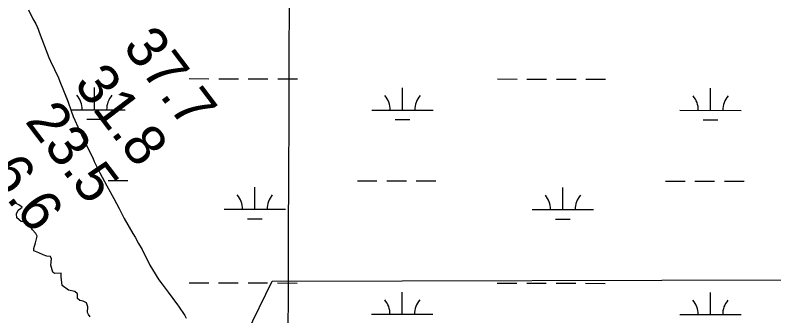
# Model space of a CAD drawing. Extents: x 3148686 to 3186545, y 916144 to 941516.
# Drawn here: x 3160368 to 3161603, y 939203 to 939693 of the extents above; entities that cross this region are included whole.
import ezdxf

# ---------------------------------------------------------------- set-up
doc = ezdxf.new("R2010")
doc.units = 0
for name, color, linetype in [('V-GRID-MAJR', 7, 'Continuous'), ('V-RIVR-EDGE', 7, 'Continuous'), ('V-RIVR-RANG', 7, 'Continuous'), ('V-SITE-VEGE', 7, 'Continuous'), ('V-TOPO-BNDY', 7, 'Continuous'), ('V-WETL-SWMP', 7, 'Continuous')]:
    doc.layers.add(name, color=color, linetype=linetype)

msp = doc.modelspace()

# ---------------------------------------------------------------- linework, layer by layer
at = {"layer": 'V-GRID-MAJR'}
msp.add_spline([(3160753.613, 921529.2320000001), (3160773.887, 927589.627), (3160794.169, 933652.633), (3160814.452, 939715.688), (3160814.461, 939718.2490000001)], degree=3, dxfattribs=at)
at = {"layer": 'V-RIVR-EDGE'}
msp.add_lwpolyline([(3160489.8511724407, 939201.590195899), (3160487.0077412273, 939205.2275865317), (3160485.7195277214, 939208.6018201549), (3160485.7413284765, 939217.4183539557), (3160483.942830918, 939224.1648976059), (3160478.2450681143, 939227.0314119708), (3160472.8014855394, 939227.8228065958), (3160469.179483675, 939231.2028110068), (3160469.198078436, 939238.7227957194), (3160464.799429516, 939242.6233433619), (3160454.6914762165, 939244.7228286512), (3160444.0783684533, 939252.2691025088), (3160442.558416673, 939266.7942994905), (3160442.572523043, 939272.4991154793), (3160431.938896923, 939271.7474751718), (3160428.8335910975, 939274.3482677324), (3160425.7500860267, 939285.7655940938), (3160426.8123320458, 939295.8761121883), (3160425.0067813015, 939299.7702478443), (3160419.30324771, 939300.30297385), (3160413.084941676, 939302.3928411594), (3160406.0912709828, 939305.5218713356), (3160398.060361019, 939308.6534663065), (3160397.81131038, 939312.8030645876), (3160400.9454701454, 939321.8712138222), (3160403.5661398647, 939333.0151239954), (3160401.5019205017, 939337.1692106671), (3160395.811852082, 939343.1474428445), (3160391.680207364, 939350.1590671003), (3160385.727623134, 939354.8413913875), (3160377.43355616, 939356.4177686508), (3160370.446938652, 939362.3992068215), (3160369.944990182, 939369.1425444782), (3160372.5528359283, 939375.100258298), (3160376.1902265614, 939377.9436895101), (3160379.306432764, 939379.7511638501), (3160373.6118759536, 939383.914227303), (3160361.1791110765, 939389.649820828)], dxfattribs=at)
at = {"layer": 'V-SITE-VEGE'}
for p, q in [((3160389.606, 939701.4709999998), (3160396.68, 939686.993)), ((3160396.6800000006, 939686.993), (3160399.6330000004, 939681.2809999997)), ((3160399.633, 939681.2809999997), (3160401.417, 939678.623)), ((3160401.4170000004, 939678.623), (3160404.9360000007, 939670.069)), ((3160404.936, 939670.069), (3160406.4760000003, 939664.7829999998)), ((3160406.4760000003, 939664.7829999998), (3160422.679, 939624.054)), ((3160422.679, 939624.054), (3160425.221, 939617.947)), ((3160425.221, 939617.947), (3160437.9760000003, 939590.426)), ((3160437.9760000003, 939590.426), (3160440.52, 939584.5169999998)), ((3160440.52, 939584.5169999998), (3160446.383, 939570.2589999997)), ((3160446.383, 939570.2589999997), (3160453.795, 939551.1209999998)), ((3160453.7950000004, 939551.1209999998), (3160458.648, 939537.0800000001)), ((3160458.648, 939537.0800000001), (3160462.1590000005, 939527.9189999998)), ((3160462.1590000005, 939527.9189999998), (3160472.346, 939504.8909999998)), ((3160472.346, 939504.8909999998), (3160482.952, 939482.8709999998)), ((3160482.952, 939482.8709999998), (3160494.1590000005, 939460.2349999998)), ((3160494.1590000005, 939460.2349999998), (3160496.508, 939454.5309999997)), ((3160496.508, 939454.5309999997), (3160499.056, 939449.028)), ((3160499.056, 939449.028), (3160505.3450000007, 939436.1809999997)), ((3160505.345, 939436.1809999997), (3160516.771, 939414.7569999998)), ((3160516.7710000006, 939414.7569999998), (3160528.213, 939394.3420000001)), ((3160528.2130000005, 939394.3420000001), (3160536.8760000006, 939377.817)), ((3160536.876, 939377.817), (3160544.9390000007, 939361.7029999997)), ((3160544.9390000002, 939361.7029999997), (3160559.1520000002, 939336.998)), ((3160559.1520000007, 939336.998), (3160562.9080000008, 939330.8709999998)), ((3160562.9080000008, 939330.8709999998), (3160568.6280000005, 939320.6649999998)), ((3160568.6280000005, 939320.6649999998), (3160574.3540000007, 939310.8619999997)), ((3160574.3540000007, 939310.8619999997), (3160578.882, 939302.09)), ((3160578.882, 939302.09), (3160584.58, 939290.2649999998)), ((3160584.58, 939290.2649999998), (3160587.142, 939285.571)), ((3160587.142, 939285.571), (3160591.287, 939278.4229999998)), ((3160591.287, 939278.4229999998), (3160601.568, 939261.6709999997)), ((3160601.568, 939261.6709999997), (3160607.333, 939254.5009999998)), ((3160607.333, 939254.5009999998), (3160617.065, 939241.8049999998)), ((3160617.065, 939241.8049999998), (3160631.9460000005, 939221.1389999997)), ((3160631.946, 939221.1389999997), (3160633.935, 939218.6789999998)), ((3160633.935, 939218.6789999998), (3160643.8310000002, 939203.3519999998)), ((3160643.8310000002, 939203.3519999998), (3160645.995, 939199.27))]:
    msp.add_line(p, q, dxfattribs=at)
at = {"layer": 'V-TOPO-BNDY'}
for p, q in [((3160786.109000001, 939259.3729999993), (3184295.4581763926, 939315.6127136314)), ((3158547.469000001, 934665.7829999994), (3160786.109000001, 939259.3729999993))]:
    msp.add_line(p, q, dxfattribs=at)
at = {"layer": 'V-WETL-SWMP'}
for p, q in [((3160389.607140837, 939701.4730764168), (3160396.682146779, 939686.9950820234)), ((3160389.607140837, 939701.4730764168), (3160396.682146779, 939686.9950820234)), ((3160396.682146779, 939686.9950820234), (3160399.6351474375, 939681.2830826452)), ((3160396.682146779, 939686.9950820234), (3160399.6351474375, 939681.2830826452)), ((3160399.6351474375, 939681.2830826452), (3160401.418147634, 939678.6250828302)), ((3160399.6351474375, 939681.2830826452), (3160401.418147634, 939678.6250828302)), ((3160401.418147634, 939678.6250828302), (3160402.787148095, 939675.3660832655)), ((3160401.418147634, 939678.6250828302), (3160402.787148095, 939675.3660832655)), ((3160402.787148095, 939675.3660832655), (3160404.936144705, 939670.0700800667)), ((3160402.787148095, 939675.3660832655), (3160404.936144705, 939670.0700800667)), ((3160404.936144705, 939670.0700800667), (3160406.4771497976, 939664.784084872)), ((3160404.936144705, 939670.0700800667), (3160406.4771497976, 939664.784084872)), ((3160406.4771497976, 939664.784084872), (3160422.6801516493, 939624.0560866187)), ((3160406.4771497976, 939664.784084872), (3160422.6801516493, 939624.0560866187)), ((3160422.6801516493, 939624.0560866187), (3160425.2221525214, 939617.9450874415)), ((3160422.6801516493, 939624.0560866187), (3160425.2221525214, 939617.9450874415)), ((3160425.2221525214, 939617.9450874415), (3160437.9761560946, 939590.4270908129)), ((3160425.2221525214, 939617.9450874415), (3160437.9761560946, 939590.4270908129)), ((3160437.9761560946, 939590.4270908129), (3160440.5211569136, 939584.5180915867)), ((3160437.9761560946, 939590.4270908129), (3160440.5211569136, 939584.5180915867)), ((3160651.2888178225, 939589.323211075), (3160683.288795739, 939589.2894925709)), ((3160699.2887846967, 939589.2726333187), (3160731.2887626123, 939589.2389148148)), ((3160747.288751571, 939589.2220555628), (3160779.2887294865, 939589.1883370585)), ((3160795.2887184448, 939589.1714778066), (3160827.288696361, 939589.1377593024)), ((3161153.1964714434, 939588.7943489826), (3161185.196449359, 939588.7606304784)), ((3161201.1964383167, 939588.7437712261), (3161233.196416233, 939588.7100527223)), ((3161249.196405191, 939588.6931934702), (3161281.196383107, 939588.6594749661)), ((3161297.1963720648, 939588.6426157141), (3161329.196349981, 939588.6088972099)), ((3160440.5211569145, 939584.5180915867), (3160446.384158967, 939570.2610935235)), ((3160440.5211569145, 939584.5180915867), (3160446.384158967, 939570.2610935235)), ((3160446.384158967, 939570.2610935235), (3160451.6521651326, 939556.8210993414)), ((3160446.384158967, 939570.2610935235), (3160451.6521651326, 939556.8210993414)), ((3160496.6434704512, 939538.7441394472), (3160496.68139458, 939574.7441151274)), ((3160998.551124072, 939538.2152773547), (3160998.5890482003, 939574.2152530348)), ((3161500.4587776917, 939537.6864152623), (3161500.4967018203, 939573.6863909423)), ((3160451.6521651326, 939556.8210993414), (3160453.795161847, 939551.121096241)), ((3160451.6521651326, 939556.8210993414), (3160453.795161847, 939551.121096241)), ((3160453.795161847, 939551.121096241), (3160458.6501641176, 939537.081098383)), ((3160453.795161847, 939551.121096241), (3160458.6501641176, 939537.081098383)), ((3160458.0610297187, 939538.7847939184), (3160546.6434359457, 939538.6914542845)), ((3160458.6501641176, 939537.081098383), (3160462.1591696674, 939527.9191036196)), ((3160458.6501641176, 939537.081098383), (3160462.1591696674, 939527.9191036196)), ((3160462.1591696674, 939527.9191036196), (3160472.3471727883, 939504.8931065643)), ((3160462.1591696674, 939527.9191036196), (3160472.3471727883, 939504.8931065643)), ((3160948.551158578, 939538.2679625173), (3161048.5510895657, 939538.162592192)), ((3161450.458812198, 939537.7391004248), (3161550.458743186, 939537.6337300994)), ((3160484.6272229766, 939523.3257943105), (3160508.6272064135, 939523.3005054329)), ((3160986.534876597, 939522.7969322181), (3161010.534860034, 939522.7716433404)), ((3161488.442530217, 939522.2680701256), (3161512.442513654, 939522.2427812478)), ((3160472.3471727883, 939504.8931065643), (3160482.9541713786, 939482.8721052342)), ((3160472.3471727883, 939504.8931065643), (3160482.9541713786, 939482.8721052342)), ((3160482.9541713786, 939482.8721052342), (3160494.1601782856, 939460.2351117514)), ((3160482.9541713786, 939482.8721052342), (3160494.1601782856, 939460.2351117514)), ((3160494.1601782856, 939460.2351117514), (3160496.506179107, 939454.5321125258)), ((3160494.1601782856, 939460.2351117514), (3160496.506179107, 939454.5321125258)), ((3160496.506179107, 939454.5321125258), (3160499.057179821, 939449.0291131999)), ((3160496.506179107, 939454.5321125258), (3160499.057179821, 939449.0291131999)), ((3160499.057179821, 939449.0291131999), (3160505.3461813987, 939436.1821146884)), ((3160499.057179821, 939449.0291131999), (3160505.3461813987, 939436.1821146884)), ((3160505.3461813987, 939436.1821146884), (3160516.772183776, 939414.7571169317)), ((3160505.3461813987, 939436.1821146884), (3160516.772183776, 939414.7571169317)), ((3160519.1138532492, 939423.288412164), (3160551.1138311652, 939423.2546936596)), ((3160925.0215731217, 939422.8607055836), (3160957.0215510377, 939422.8269870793)), ((3160973.0215399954, 939422.8101278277), (3161005.0215179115, 939422.7764093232)), ((3161021.0215068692, 939422.7595500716), (3161053.0214847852, 939422.7258315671)), ((3161426.9292267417, 939422.3318434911), (3161458.929204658, 939422.2981249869)), ((3161474.929193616, 939422.2812657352), (3161506.929171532, 939422.2475472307)), ((3161522.9291604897, 939422.230687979), (3161554.9291384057, 939422.1969694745)), ((3160516.772183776, 939414.7571169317), (3160528.2131858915, 939394.3431189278)), ((3160516.772183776, 939414.7571169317), (3160528.2131858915, 939394.3431189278)), ((3160757.9087768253, 939376.6067728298), (3160757.946700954, 939412.6067485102)), ((3161259.8164304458, 939376.0779107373), (3161259.8543545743, 939412.0778864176)), ((3160528.2131858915, 939394.3431189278), (3160536.8771877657, 939377.8171206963)), ((3160528.2131858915, 939394.3431189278), (3160536.8771877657, 939377.8171206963)), ((3160536.8771877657, 939377.8171206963), (3160544.9401855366, 939361.7051185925)), ((3160536.8771877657, 939377.8171206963), (3160544.9401855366, 939361.7051185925)), ((3160707.9088113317, 939376.6594579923), (3160807.9087423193, 939376.5540876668)), ((3161209.8164649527, 939376.1305958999), (3161309.8163959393, 939376.0252255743)), ((3160544.9401855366, 939361.7051185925), (3160559.153192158, 939337.0001248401)), ((3160544.9401855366, 939361.7051185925), (3160559.153192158, 939337.0001248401)), ((3160745.8925293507, 939361.1884276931), (3160769.8925127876, 939361.1631388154)), ((3161247.800182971, 939360.6595656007), (3161271.8001664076, 939360.6342767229)), ((3160559.153192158, 939337.0001248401), (3160562.9091885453, 939330.8711214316)), ((3160559.153192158, 939337.0001248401), (3160562.9091885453, 939330.8711214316)), ((3160562.9091885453, 939330.8711214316), (3160568.6291937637, 939320.6641263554)), ((3160562.9091885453, 939330.8711214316), (3160568.6291937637, 939320.6641263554)), ((3160568.6291937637, 939320.6641263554), (3160574.3561905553, 939310.8631233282)), ((3160568.6291937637, 939320.6641263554), (3160574.3561905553, 939310.8631233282)), ((3160574.3561905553, 939310.8631233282), (3160578.8831915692, 939302.0911242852)), ((3160574.3561905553, 939310.8631233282), (3160578.8831915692, 939302.0911242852)), ((3160578.8831915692, 939302.0911242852), (3160584.5801930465, 939290.2651256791)), ((3160578.8831915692, 939302.0911242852), (3160584.5801930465, 939290.2651256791)), ((3160584.5801930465, 939290.2651256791), (3160587.1431977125, 939285.571130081)), ((3160584.5801930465, 939290.2651256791), (3160587.1431977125, 939285.571130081)), ((3160587.1431977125, 939285.571130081), (3160591.289194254, 939278.4241268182)), ((3160587.1431977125, 939285.571130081), (3160591.289194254, 939278.4241268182)), ((3160591.289194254, 939278.4241268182), (3160601.5691957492, 939261.6721282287)), ((3160591.289194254, 939278.4241268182), (3160601.5691957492, 939261.6721282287)), ((3160601.5691957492, 939261.6721282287), (3160607.3342001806, 939254.50113241)), ((3160601.5691957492, 939261.6721282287), (3160607.3342001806, 939254.50113241)), ((3160650.9383620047, 939256.6484358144), (3160682.938339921, 939256.6147173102)), ((3160698.938328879, 939256.5978580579), (3160730.9383067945, 939256.564139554)), ((3160746.9382957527, 939256.547280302), (3160778.9382736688, 939256.5135617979)), ((3160794.9382626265, 939256.4967025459), (3160826.9382405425, 939256.4629840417)), ((3161152.846015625, 939256.1195737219), (3161184.845993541, 939256.0858552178)), ((3161200.8459824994, 939256.0689959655), (3161232.845960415, 939256.0352774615)), ((3161248.845949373, 939256.0184182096), (3161280.845927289, 939255.9846997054)), ((3161296.845916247, 939255.9678404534), (3161328.845894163, 939255.9341219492)), ((3160607.3342001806, 939254.50113241), (3160617.067196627, 939241.806129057)), ((3160607.3342001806, 939254.50113241), (3160617.067196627, 939241.806129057)), ((3160617.067196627, 939241.806129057), (3160631.9471978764, 939221.1401302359)), ((3160617.067196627, 939241.806129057), (3160631.9471978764, 939221.1401302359)), ((3160998.200668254, 939205.5405020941), (3160998.2385923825, 939241.5404777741)), ((3161500.1083218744, 939205.0116400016), (3161500.1462460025, 939241.0116156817)), ((3160631.9471978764, 939221.1401302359), (3160633.9351979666, 939218.6811303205)), ((3160631.9471978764, 939221.1401302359), (3160633.9351979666, 939218.6811303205)), ((3160633.9351979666, 939218.6811303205), (3160643.8311992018, 939203.3521314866)), ((3160633.9351979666, 939218.6811303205), (3160643.8311992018, 939203.3521314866)), ((3160948.2007027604, 939205.5931872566), (3161048.200633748, 939205.4878169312)), ((3160643.8311992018, 939203.3521314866), (3160645.9982038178, 939199.2711358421)), ((3160643.8311992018, 939203.3521314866), (3160645.9982038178, 939199.2711358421)), ((3161450.1083563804, 939205.0643251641), (3161550.1082873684, 939204.9589548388))]:
    msp.add_line(p, q, dxfattribs=at)
for centre, radius, start, end in [((3160441.4010726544, 939539.2771519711), 35.24628790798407, 359.16780716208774, 40.71146549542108), ((3160551.88686861, 939539.1607326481), 35.246287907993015, 139.1678041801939, 180.71146251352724), ((3160943.3087262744, 939538.7482898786), 35.24628790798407, 359.16780716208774, 40.71146549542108), ((3161053.79452223, 939538.6318705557), 35.246287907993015, 139.1678041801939, 180.71146251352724), ((3161445.216379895, 939538.2194277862), 35.24628790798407, 359.16780716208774, 40.71146549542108), ((3161555.7021758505, 939538.1030084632), 35.246287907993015, 139.1678041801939, 180.71146251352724), ((3160702.6663790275, 939377.1397853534), 35.24628790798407, 359.16780716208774, 40.71146549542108), ((3160813.1521749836, 939377.0233660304), 35.246287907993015, 139.1678041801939, 180.71146251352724), ((3161204.574032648, 939376.6109232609), 35.24628790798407, 359.16780716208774, 40.71146549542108), ((3161315.0598286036, 939376.494503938), 35.246287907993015, 139.1678041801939, 180.71146251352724), ((3160942.9582704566, 939206.073514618), 35.24628790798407, 359.16780716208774, 40.71146549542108), ((3161053.444066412, 939205.957095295), 35.246287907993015, 139.1678041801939, 180.71146251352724), ((3161444.865924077, 939205.5446525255), 35.24628790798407, 359.16780716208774, 40.71146549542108), ((3161555.3517200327, 939205.4282332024), 35.246287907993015, 139.1678041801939, 180.71146251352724)]:
    msp.add_arc(centre, radius, start, end, dxfattribs=at)

# ---------------------------------------------------------------- texts
at = {"layer": 'V-RIVR-RANG'}
for s, p in [('37.7', (3160541.50302781, 939641.0305349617)), ('31.8', (3160461.9940278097, 939580.3815349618)), ('23.5', (3160382.4850278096, 939519.7325349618)), ('6.6', (3160321.9525205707, 939434.081094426))]:
    msp.add_text(s, height=67, rotation=307.1983257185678, dxfattribs=at).set_placement(p)

doc.saveas('drawing.dxf')
